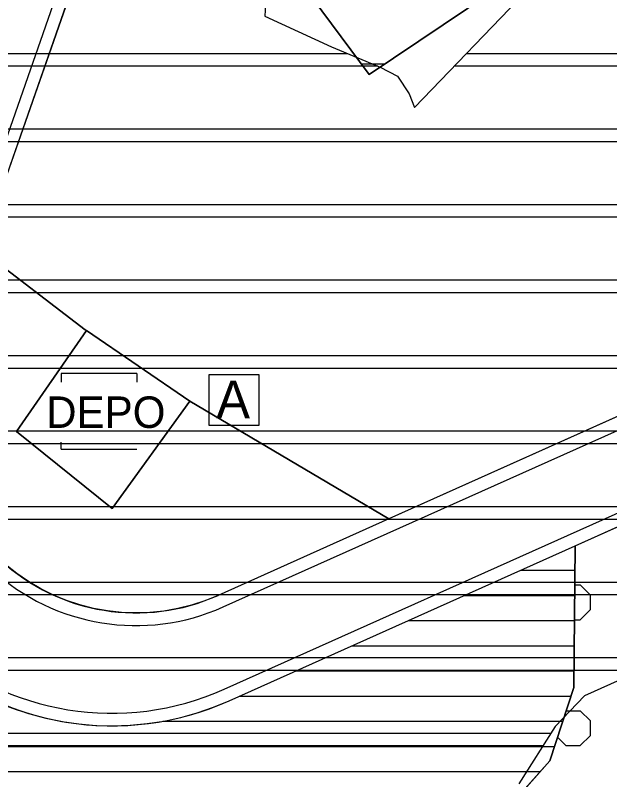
# Model space of a CAD drawing. Extents: x 427903 to 430077, y 4477233 to 4480385.
# Drawn here: x 428734.1 to 428970.2, y 4478522.4 to 4478826.1 of the extents above; entities that cross this region are included whole.
import ezdxf

# ---------------------------------------------------------------- set-up
doc = ezdxf.new("R2010")
doc.units = 0
for name, color, linetype in [('ADAKENARI', 7, 'Continuous'), ('KALDIRIM', 7, 'Continuous'), ('PL_AYA_AGACLANDIRIL', 7, 'Continuous'), ('PL_AYA_BOLGE_PARKI', 7, 'Continuous'), ('PL_AYA_PARK_DINLENME', 7, 'Continuous'), ('PL_KON_ONE_100', 7, 'Continuous'), ('PL_KON_ONE_250', 7, 'Continuous'), ('PL_SU_DEPOSU', 7, 'Continuous'), ('S_SIT', 7, 'Continuous'), ('SIT_1_DER_ARKEOLOJIK', 7, 'Continuous'), ('TR_2_SITKORUMA', 7, 'Continuous'), ('TR_AGACALANI', 7, 'Continuous'), ('TR_AZYOGUNKONUT', 7, 'Continuous'), ('TR_ORTAGELISME', 7, 'Continuous'), ('XSIT', 7, 'Continuous')]:
    doc.layers.add(name, color=color, linetype=linetype)

msp = doc.modelspace()

# ---------------------------------------------------------------- linework, layer by layer
at = {"layer": 'ADAKENARI'}
for p, q in [((428720.37, 4478732.95), (428771.09, 4478878)), ((428874.66, 4478802.53), (428962.79, 4478861.97)), ((428833.67, 4478857.87), (428874.66, 4478802.53)), ((428720.37, 4478732.95), (428761.91, 4478701.21)), ((429070.09, 4478710.12), (428882.45, 4478626.03)), ((428734.56, 4478660.77), (428762.4, 4478700.9)), ((428761.91, 4478701.21), (428762.4, 4478700.9)), ((428762.4, 4478700.9), (428803.5, 4478672.88)), ((428803.5, 4478672.88), (428772.64, 4478630.13)), ((428803.5, 4478672.88), (428882.45, 4478626.03)), ((428956.49, 4478615.38), (429086.45, 4478673.61)), ((428772.64, 4478630.13), (428734.56, 4478660.77)), ((428882.45, 4478626.03), (428814.66, 4478595.66)), ((428819.12, 4478553.82), (428956.49, 4478615.38)), ((428955.96, 4478559.13), (428956.49, 4478615.38)), ((428946.33, 4478529.89), (428955.96, 4478559.13)), ((428933.08, 4478515.04), (428946.33, 4478529.89))]:
    msp.add_line(p, q, dxfattribs=at)
for centre, radius in [((428772.5, 4478657.85), 114), ((428782.11, 4478668.31), 79.61)]:
    msp.add_arc(centre, radius, 160.7273, 294.1375, dxfattribs=at)
at = {"layer": 'KALDIRIM'}
for p, q in [((428766.37, 4478879.65), (428702.2, 4478696.13)), ((428816.61, 4478591.05), (428973.2, 4478661.22)), ((428817.07, 4478558.38), (428988.88, 4478635.37))]:
    msp.add_line(p, q, dxfattribs=at)
for centre, radius in [((428782.03, 4478668.22), 84.56), ((428772.5, 4478657.85), 109)]:
    msp.add_arc(centre, radius, 160.7273, 294.1375, dxfattribs=at)
at = {"layer": 'PL_AYA_AGACLANDIRIL'}
msp.add_lwpolyline([(428970.84, 4478413.08), (428966.93, 4478411.95), (428962.93, 4478411.25), (428958.87, 4478410.98), (428954.81, 4478411.14), (428950.79, 4478411.73), (428946.85, 4478412.76), (428943.05, 4478414.19), (428873.66, 4478444.73), (428933.08, 4478515.04), (428946.33, 4478529.89), (428955.96, 4478559.13), (428956.49, 4478615.38), (429086.45, 4478673.61)], dxfattribs=at)
at = {"layer": 'PL_AYA_BOLGE_PARKI'}
msp.add_lwpolyline([(428833.67, 4478857.87), (428874.66, 4478802.53), (428962.79, 4478861.97), (428999.68, 4478767.69), (429065.26, 4478782.03), (429116.59, 4478726.76), (429070.09, 4478710.12), (428882.45, 4478626.03), (428803.5, 4478672.88), (428762.4, 4478700.9), (428761.91, 4478701.21), (428720.37, 4478732.95), (428771.09, 4478878)], dxfattribs=at)
at = {"layer": 'PL_AYA_PARK_DINLENME'}
msp.add_lwpolyline([(428720.37, 4478732.95), (428761.91, 4478701.21), (428762.4, 4478700.9), (428734.56, 4478660.77), (428772.64, 4478630.13), (428803.5, 4478672.88), (428882.45, 4478626.03), (428814.66, 4478595.66), (428809.46, 4478593.54), (428804.12, 4478591.8), (428798.67, 4478590.44), (428793.14, 4478589.46), (428787.56, 4478588.88), (428781.94, 4478588.7), (428776.33, 4478588.91), (428770.75, 4478589.51), (428765.22, 4478590.51), (428759.78, 4478591.89), (428754.45, 4478593.66), (428749.25, 4478595.79), (428744.22, 4478598.29), (428739.38, 4478601.14), (428734.75, 4478604.31), (428730.35, 4478607.81)], dxfattribs=at)
at = {"layer": 'PL_KON_ONE_100'}
msp.add_lwpolyline([(428962.79, 4478861.97), (428874.66, 4478802.53), (428833.67, 4478857.87)], dxfattribs=at)
at = {"layer": 'PL_KON_ONE_250'}
msp.add_lwpolyline([(428710.95, 4478561.96), (428714.48, 4478559.72), (428720.44, 4478556.44), (428726.58, 4478553.51), (428732.89, 4478550.96), (428739.34, 4478548.79), (428745.91, 4478547), (428752.57, 4478545.61), (428759.3, 4478544.62), (428766.08, 4478544.04), (428772.88, 4478543.86), (428779.69, 4478544.08), (428786.46, 4478544.71), (428793.19, 4478545.75), (428799.84, 4478547.18), (428806.39, 4478549.01), (428812.83, 4478551.23), (428819.12, 4478553.82), (428956.49, 4478615.38), (428955.96, 4478559.13), (428946.33, 4478529.89), (428933.08, 4478515.04)], dxfattribs=at)
at = {"layer": 'PL_SU_DEPOSU'}
msp.add_lwpolyline([(428803.5, 4478672.88), (428772.64, 4478630.13), (428734.56, 4478660.77), (428762.4, 4478700.9)], close=True, dxfattribs=at)
at = {"layer": 'S_SIT'}
for p, q in [((428831.01, 4478683.31), (428811.01, 4478683.31)), ((428811.01, 4478683.31), (428811.01, 4478663.31)), ((428831.01, 4478663.31), (428831.01, 4478683.31)), ((428811.01, 4478663.31), (428831.01, 4478663.31))]:
    msp.add_line(p, q, dxfattribs=at)
at = {"layer": 'SIT_1_DER_ARKEOLOJIK'}
for points in [[(428833.85, 4478837.77), (428833.16, 4478825.72), (428859.7, 4478813.55), (428879.06, 4478805.55), (428885.9, 4478801.95), (428890.53, 4478794.88), (428892.62, 4478789.44), (428937.25, 4478835.92)], [(428989.99, 4478569.08), (428960.08, 4478555.75), (428948.49, 4478543.58), (428934.12, 4478520.74)]]:
    msp.add_lwpolyline(points, dxfattribs=at)
at = {"layer": 'TR_2_SITKORUMA'}
for p, q in [((428584.5, 4478810.98), (428865.92, 4478810.98)), ((428913.3, 4478810.98), (428989.9, 4478810.98)), ((428581.64, 4478805.98), (428878.02, 4478805.98)), ((428908.5, 4478805.98), (428990.37, 4478805.98)), ((428564.51, 4478780.98), (428991.86, 4478780.98)), ((428561.27, 4478775.98), (428992, 4478775.98)), ((428654.39, 4478750.98), (429095.32, 4478750.98)), ((428659.45, 4478745.98), (429099.52, 4478745.98)), ((428662.5, 4478720.98), (429117.4, 4478720.98)), ((428659.62, 4478715.98), (429118.14, 4478715.98)), ((428602.58, 4478690.98), (429143.59, 4478690.98)), ((428606.17, 4478685.98), (429150.11, 4478685.98)), ((428600.5, 4478660.98), (429168.33, 4478660.98)), ((428599.13, 4478655.98), (428804.8, 4478655.98)), ((428804.8, 4478655.98), (429171.76, 4478655.98)), ((428585.18, 4478630.98), (428785.91, 4478630.98)), ((428785.91, 4478630.98), (429199.68, 4478630.98)), ((428581.47, 4478625.98), (428786.57, 4478625.98)), ((428786.57, 4478625.98), (429004.19, 4478625.98)), ((428566.25, 4478600.98), (429013.98, 4478600.98)), ((428563.95, 4478595.98), (429010.94, 4478595.98)), ((428552.33, 4478570.98), (428991.48, 4478570.98)), ((428550.05, 4478565.98), (428983.03, 4478565.98)), ((428584.49, 4478540.98), (428946.86, 4478540.98)), ((428592.26, 4478535.98), (428943.71, 4478535.98))]:
    msp.add_line(p, q, dxfattribs=at)
at = {"layer": 'TR_AGACALANI'}
for p, q in [((428956.35, 4478599.84), (428958.48, 4478599.84)), ((428962.52, 4478595.79), (428958.46, 4478599.85)), ((428962.52, 4478590.06), (428962.52, 4478595.8)), ((428958.48, 4478585.97), (428962.54, 4478590.03)), ((428956.22, 4478585.98), (428958.48, 4478585.98)), ((428952.9, 4478549.84), (428958.48, 4478549.84)), ((428962.52, 4478545.79), (428958.46, 4478549.85)), ((428962.52, 4478540.06), (428962.52, 4478545.8)), ((428952.74, 4478535.98), (428949.43, 4478539.29)), ((428958.48, 4478535.98), (428962.54, 4478540.03)), ((428952.74, 4478535.98), (428958.48, 4478535.98))]:
    msp.add_line(p, q, dxfattribs=at)
at = {"layer": 'TR_AZYOGUNKONUT'}
msp.add_line((428871.52, 4478806.76), (428880.93, 4478806.76), dxfattribs=at)
at = {"layer": 'TR_ORTAGELISME'}
for p, q in [((428934.85, 4478605.68), (428956.4, 4478605.68)), ((428912.53, 4478595.68), (428956.31, 4478595.68)), ((428890.22, 4478585.68), (428956.21, 4478585.68)), ((428890.22, 4478585.68), (428956.21, 4478585.68)), ((428867.9, 4478575.68), (428956.12, 4478575.68)), ((428867.9, 4478575.68), (428956.12, 4478575.68)), ((428845.59, 4478565.68), (428956.02, 4478565.68)), ((428845.59, 4478565.68), (428956.02, 4478565.68)), ((428823.27, 4478555.68), (428954.83, 4478555.68)), ((428823.27, 4478555.68), (428954.83, 4478555.68)), ((428792.77, 4478545.68), (428951.53, 4478545.68)), ((428792.77, 4478545.68), (428951.53, 4478545.68)), ((428686.57, 4478535.68), (428948.24, 4478535.68)), ((428695.63, 4478525.68), (428942.57, 4478525.68))]:
    msp.add_line(p, q, dxfattribs=at)
at = {"layer": 'XSIT'}
for p, q in [((428782.34, 4478683.77), (428752.34, 4478683.77)), ((428752.34, 4478683.77), (428752.34, 4478680.4)), ((428782.34, 4478683.77), (428782.34, 4478680.4)), ((428752.34, 4478653.77), (428752.34, 4478656.55)), ((428752.34, 4478653.77), (428782.34, 4478653.77))]:
    msp.add_line(p, q, dxfattribs=at)

# ---------------------------------------------------------------- texts
at = {"layer": 'S_SIT'}
msp.add_text('A', height=15, dxfattribs=at).set_placement((428813.95, 4478665.99))
at = {"layer": 'XSIT'}
msp.add_text('DEPO', height=12.5, dxfattribs=at).set_placement((428746.39, 4478662.19))

doc.saveas('drawing.dxf')
